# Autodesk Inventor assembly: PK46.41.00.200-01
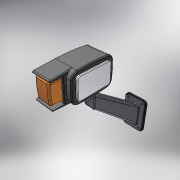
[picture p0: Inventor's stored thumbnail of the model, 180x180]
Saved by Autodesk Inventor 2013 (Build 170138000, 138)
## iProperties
Created: 2005-07
Part Number: PK46.41.00.200-01
Document SubType Name: Assembly
Designer: PVitaliy
Manufacturer: Standard
Standards Organization: Custom
Author: PVitaliy
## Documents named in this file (8)
- C:\Product Design Suite 2013 Test Drive\Dynamic Simulation\Workspace\Assy, Chassis, Front\PK46.41.00.200-01.iam
- C:\Product Design Suite 2013 Test Drive\Dynamic Simulation\Workspace\Assy, Chassis, Front\05.483.000-01.ipt
- C:\Product Design Suite 2013 Test Drive\Dynamic Simulation\Workspace\Assy, Chassis, Front\D395A-0401269-01.ipt
- C:\Product Design Suite 2013 Test Drive\Dynamic Simulation\Workspace\Assy, Chassis, Front\PK46.41.00.210-01.iam
- C:\Product Design Suite 2013 Test Drive\Dynamic Simulation\Workspace\Assy, Chassis, Front\10.65G.019.ipt
- C:\Product Design Suite 2013 Test Drive\Dynamic Simulation\Workspace\Assy, Chassis, Front\M10-6H.5.019(S16).ipt
- C:\Product Design Suite 2013 Test Drive\Dynamic Simulation\Workspace\Assy, Chassis, Front\D395A-0401270.ipt
- C:\Product Design Suite 2013 Test Drive\Dynamic Simulation\Workspace\Assy, Chassis, Front\PK46.21.01.093.ipt
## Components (7 placed, 7 different names)
1. PK46.41.00.210-01:1 [sub-assembly] — Insert:7, Insert:8, Insert:9, Insert:11
2. 05.483.000-01:1
3. PK46.21.01.093:1 — Insert:7, Insert:8
4. D395A-0401269-01:1
5. 10.65G.019:1 — Insert:9, Insert:10
6. M10-6H.5.019(S16):1 — Insert:10
7. D395A-0401270:1 — Insert:11
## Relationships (5: Insert 5)
- Insert:7: PK46.41.00.210-01:1 ↔ PK46.21.01.093:1
- Insert:8: PK46.41.00.210-01:1 ↔ PK46.21.01.093:1
- Insert:9: PK46.41.00.210-01:1 ↔ 10.65G.019:1
- Insert:10: 10.65G.019:1 ↔ M10-6H.5.019(S16):1
- Insert:11: PK46.41.00.210-01:1 ↔ D395A-0401270:1
